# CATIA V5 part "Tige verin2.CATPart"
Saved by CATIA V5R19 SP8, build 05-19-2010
Part number: Tige verin2
Bounding box of the stored display mesh (mm): x 46.439 to 93.5, y 46.5 to 55.5, z 3.5 to 79.456
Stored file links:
  G:\EU_thinkMotion\CFAO_2010\MMS_groupe1\MMS_groupe1\A reprendre\OK\glenerrant\glenerrant\glenerrant\Tige verin2.CATPart
  C:\Users\Gauthier\Documents\IFMA\Projet CFAO\glenerrant\Systeme.CATProduct
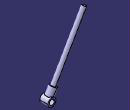
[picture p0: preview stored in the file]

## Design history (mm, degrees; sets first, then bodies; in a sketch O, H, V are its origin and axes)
Parameters
  `Longueur tige verin 2` = 69 mm {= `External.Longueur tige verin t`}
External parameters (linked from other documents)
  `External.Longueur tige verin t` = 69 mm
Set1
  Point1: (89, 51, 8)
  Point2: (5, 51, 154)
  Line1: type PtPt, FirstPoint Point1, SecondPoint Point2
  Plane1: type Normal, Curve Line1, RefPoint Point1
  Plane2: type Offset, RefPlane zx-plane, Offset 46.5
Body1 (main body)
  Sketch1 on Plane2, origin (0, 46.5, 0), H (-1, 0, 0), V (0, 0, 1)
    circle A1 centre (-89, 8) radius 4.5
    point P1 (-89, 8)
    circle A2 centre (-89, 8) radius 3
    point P2 (-89, 8)
    reference projected point E1 (-89, 8) from Point1
    reference projected point E2 (-89, 8) from Point1
    radius A1 = 4.5
    radius A2 = 3
    coincidence: P2 E1, P1 E2
  Pad1: profile Sketch1, direction (0, 1, 0), length 9
  Sketch2 on Plane1, origin (18.6759, 0, -32.4605), H (0, -1, 0), V (0.8668, 0, 0.4987)
    circle A1 centre (-51, 81.1328) radius 4
    point P1 (-51, 81.1328)
    reference projected point E1 (-51, 81.1328) from Point1
    radius A1 = 4
    coincidence: P1 E1
  Pad2: profile Sketch2, direction (-0.4987, 0, 0.8668), length 12, opposite side length -3
  Sketch3 on end face of Pad2, origin (12.6915, 0, -22.0591), H (0, -1, 0), V (0.8668, 0, 0.4987)
    circle A1 centre (-51, 81.1328) radius 2.5
    point P1 (-51, 81.1328)
    reference projected point E1 (-51, 81.1328) from Point1
    radius A1 = 2.5
    coincidence: P1 E1
  Pad3: profile Sketch3, direction (-0.4987, 0, 0.8668), length 69 {= `Longueur tige verin 2`}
